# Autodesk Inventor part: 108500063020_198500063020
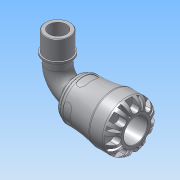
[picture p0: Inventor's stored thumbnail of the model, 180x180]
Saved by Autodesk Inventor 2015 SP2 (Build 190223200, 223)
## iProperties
Created: 2016-12
Part Number: 108500063020_198500063020
Material: PVC-Piping
Description: PLASSON 90° ELBOW WITH THREADED MALE OFFTAKE 63X2" SERIES 1
Document SubType Name: Modeling
Designer: KIM
Mass: 664.223 g
Surface Area: 733.008 cm^2
Volume: 474.445 cm^3
Density: 1.4 g/cm^3
Appearance: Smooth - White
Author: KIM
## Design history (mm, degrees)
derived "1085.ipt"
feature "Solid1::1085.ipt"
tag "TaggingFeature1"
body "Solid1"
other parameters: "d1" = 37.8, "d2" = 63, "d3" = 78.75, "d4" = 103, "d8" = 87.55, "d13" = 9.7, "d14" = 9.7, "d15" = 0, "d17" = 360 deg, "d19" = 8 deg, "d20" = 1.26, "d21" = 1.26, "d22" = 8 deg, "d24" = 0, "d26" = 360 deg, "d33" = 10.3, "d43" = 80.34, "d51" = 1.03, "d54" = 22.05, "d55" = 13.86, "d57" = 19.012, "d58" = 0, "d74" = 0, "d82" = 1.26, "d115" = 360 deg, "d207" = 90 deg, "d228" = 18.7425, "d247" = 2.06, "d248" = 5.4, "d268" = 48.1525, "d269" = 5.4, "d270" = 143, "d276" = 59.614, "d277" = 25, "d278" = 65.5754, "d279" = 81, "d280" = 27.5, "d281" = 8.9421, "d283" = 53.6526, "d286" = 0, "d287" = 0, "d288" = 41.7298, "d290" = 13.3437, "d292" = 30 deg, "d_" = 63, "E_" = 103, "A_" = 143, "A_1" = 81, "l_2" = 25, "R_" = 59.614, "d9" = 12.125, "d11" = 103, "d12" = 78.75, "d289" = 41.7298
